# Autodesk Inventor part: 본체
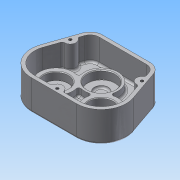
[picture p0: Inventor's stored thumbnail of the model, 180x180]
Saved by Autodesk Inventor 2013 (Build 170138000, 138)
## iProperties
Created: 2014-12
Part Number: 본체
Material: 알루미늄 6061
Document SubType Name: Modeling
Designer: Administrator
Mass: 613.435 g
Surface Area: 665.181 cm^2
Volume: 226.36 cm^3
Density: 2.71 g/cm^3
Author: Administrator
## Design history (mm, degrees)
sketch "스케치1"
  geometry: L1 (0, 32.527)-(-32.527, 0); L2 (0, 32.527)-(32.527, 0); L3 (47, 68.527)-(-47, 68.527); L4 (-66.565, 11.723)-(-47, 68.527); L5 (66.565, 11.723)-(47, 68.527); L6 (-32.527, -36)-(32.527, -36); A1 r 36 centre (-32.527, 0) between (-66.565, 11.723) and (-32.527, -36); A2 r 36 centre (32.527, 0) between (32.527, -36) and (66.565, 11.723); 1 further point
  constraints: 12 end point, 4 point on circle, 4 tangent, 2 centre point, 2 horizontal alignment, 1 equal length, 1 horizontal, 1 vertical alignment
  dimensions: "d0" = 72 diameter of A1; "d1" = 72 diameter of A2; "d3" = 90 deg angle of L1 L2; "d4" = 36 distance from line of L3 L1.start; "d5" = 94 distance of L3.start L3.end; "d25" = 46 distance of L1.start L1.end; "d26" = 46 distance of L1.start L2.end
extrude "돌출1" new body sketch "스케치1" distance "d6" = 44; taper "d7" = 0 deg
fillet "모깎기1" dims "d8" = 18
sketch "스케치2"
  geometry: L1 (-51.181, 56.389)-(-66.565, 11.723) reference; L2 (-32.527, -36)-(32.527, -36) reference; L3 (66.565, 11.723)-(51.181, 56.389) reference; L4 (34.162, 68.527)-(-34.162, 68.527) reference; L5 (-46.453, 54.76)-(-61.837, 10.095); L6 (-32.527, -31)-(32.527, -31); L7 (61.837, 10.095)-(46.453, 54.76); L8 (34.162, 63.527)-(-34.162, 63.527); A1 r 18 centre (-34.162, 50.527) between (-34.162, 68.527) and (-51.181, 56.389) reference; A2 r 36 centre (-32.527, 0) between (-66.565, 11.723) and (-32.527, -36) reference; A3 r 36 centre (32.527, 0) between (32.527, -36) and (66.565, 11.723) reference; A4 r 18 centre (34.162, 50.527) between (51.181, 56.389) and (34.162, 68.527) reference; A5 r 13 centre (-34.162, 50.527) between (-34.162, 63.527) and (-46.453, 54.76); A6 r 31 centre (-32.527, 0) between (-61.837, 10.095) and (-32.527, -31); A7 r 31 centre (32.527, 0) between (32.527, -31) and (61.837, 10.095); A8 r 13 centre (34.162, 50.527) between (46.453, 54.76) and (34.162, 63.527); 1 further point
  constraints: 8 end point, 8 point on circle, 4 centre point, 7 other
  dimensions: "d9" = 5 distance between parallel lines of L4 L8
extrude "돌출2" cut sketch "스케치2" distance "d11" = 34; taper "d12" = 0 deg
sketch "스케치3"
  geometry: L1 (-61.837, 10.095)-(-46.453, 54.76) reference; L2 (32.527, -31)-(-32.527, -31) reference; L3 (46.453, 54.76)-(61.837, 10.095) reference; L4 (-34.162, 68.527)-(34.162, 68.527) reference; A1 r 8 centre (-51.7, 39.527) between (-54.305, 31.963) and (-49.095, 47.091); A2 r 8 centre (51.7, 39.527) between (49.095, 47.091) and (54.305, 31.963); A3 r 8 centre (0, -31) between (8, -31) and (-8, -31); 1 further point
  constraints: 8 point on line, 6 point on circle, 3 centre point, 1 midpoint
  dimensions: "d13" = 16 diameter of A1; "d15" = 16 diameter of A2; "d16" = 29 distance from line of L4 A2.centre; "d17" = 29 distance from line of L4 A1.centre; "d18" = 16 diameter of A3
extrude "돌출3" join sketch "스케치3" distance "d19" = 34; taper "d20" = 0 deg
sketch "스케치4"
  geometry: C1 r 24 at (-32.527, 0); C2 r 24 at (32.527, 0); A1 r 31 centre (32.527, 0) between (32.527, -31) and (61.837, 10.095) reference; A2 r 31 centre (-32.527, 0) between (-61.837, 10.095) and (-32.527, -31) reference; 1 further point
  constraints: 2 centre point, 2 coincident
  dimensions: "d21" = 48 diameter of C1; "d22" = 48 diameter of C2
extrude "돌출4" join sketch "스케치4" distance "d23" = 11; taper "d24" = 0 deg
sketch "스케치5"
  geometry: C1 r 24 at (0, 0) reference; C2 r 24 at (-65.054, 0) reference; 1 further point
hole "구멍1" sketch "스케치5" at (-65.054, 0), (0, 0) diameter "d27" = 15.5; stored, may be unused: countersink angle "d31" = 90 deg, drill point angle "d33" = 0 deg; dims "d28" = 6, "d29" = 35, "d30" = 11, "d32" = 21
sketch "스케치6"
  geometry: C1 r 20 at (-32.527, 0); C2 r 20 at (32.527, 0); A1 r 36 centre (-32.527, 0) between (-66.565, 11.723) and (-32.527, -36) reference; A2 r 36 centre (32.527, 0) between (32.527, -36) and (66.565, 11.723) reference; 1 further point
  constraints: 2 centre point, 2 coincident
  dimensions: "d34" = 40 diameter of C1; "d35" = 40 diameter of C2
extrude "돌출5" join sketch "스케치6" distance "d36" = 7; taper "d37" = -10 deg
sketch "스케치7"
  geometry: C1 r 18.766 at (0, 0) reference; C2 r 18.766 at (65.054, 0) reference; 1 further point
hole "구멍2" sketch "스케치7" at (0, 0), (65.054, 0) diameter "d38" = 30; stored, may be unused: countersink angle "d42" = 90 deg, drill point angle "d44" = 0 deg; dims "d39" = 6, "d40" = 35, "d41" = 11, "d43" = 7
sketch "스케치8"
  geometry: L1 (-32.527, 0)-(0, 32.527); L2 (0, 32.527)-(32.527, 0); C1 r 24 at (0, 32.527); A1 r 31 centre (32.527, 0) between (32.527, -31) and (61.837, 10.095) reference; A2 r 31 centre (-32.527, 0) between (-61.837, 10.095) and (-32.527, -31) reference; 1 further point
  constraints: 4 end point, 1 centre point, 1 coincident, 1 perpendicular, 1 vertical alignment
  dimensions: "d45" = 46 distance of L1.end L2.end; "d46" = 48 diameter of C1
extrude "돌출6" join sketch "스케치8" distance "d47" = 11; taper "d48" = 0 deg
hole "구멍3" diameter "d51" = 20; stored, may be unused: countersink angle "d55" = 90 deg, drill point angle "d57" = 0 deg; dims "d49" = 10, "d50" = 10, "d52" = 6, "d53" = 40, "d54" = 12, "d56" = 15
fillet "모깎기2" dims "d58" = 0.3
fillet "모깎기3" dims "d59" = 0.1
chamfer "모따기1" distance "d60" = 1; stored, may be unused: second distance "d61" = 2, angle "d62" = 45 deg
fillet "모깎기4" dims "d63" = 3
fillet "모깎기5" dims "d64" = 3
fillet "모깎기6" dims "d65" = 3
fillet "모깎기7" dims "d66" = 3
sketch "스케치9"
  geometry: A1 r 8 centre (-51.7, 39.527) between (-52.144, 31.539) and (-47.131, 46.094) reference; A2 r 8 centre (51.7, 39.527) between (47.131, 46.094) and (52.144, 31.539) reference; A3 r 8 centre (0, -31) between (7.697, -28.818) and (-7.697, -28.818) reference; 4 further points
  constraints: 3 coincident
hole "구멍4" sketch "스케치9" at (-51.7, 39.527), (0, -31), (51.7, 39.527) diameter "d67" = 4.134; stored, may be unused: countersink angle "d71" = 90 deg, drill point angle "d73" = 118 deg; dims "d68" = 20, "d69" = 40, "d70" = 12, "d72" = 23
sketch "스케치10"
  geometry: L1 (34.162, 68.527)-(-34.162, 68.527); L2 (51.181, 56.389)-(66.565, 11.723) reference; L3 (32.527, -36)-(-32.527, -36) reference; L4 (-66.565, 11.723)-(-51.181, 56.389) reference; L5 (-34.162, 68.527)-(34.162, 68.527) reference; C1 r 14.9 at (32.527, 0) reference; C2 r 14.9 at (-32.527, 0) reference; C3 r 20 at (-32.527, 0) reference; C4 r 20 at (32.527, 0) reference; C5 r 7.75 at (32.527, 0) reference; C6 r 7.75 at (-32.527, 0) reference; A1 r 18 centre (34.162, 50.527) between (51.181, 56.389) and (34.162, 68.527) reference; A2 r 36 centre (32.527, 0) between (32.527, -36) and (66.565, 11.723) reference; A3 r 36 centre (-32.527, 0) between (-66.565, 11.723) and (-32.527, -36) reference; A4 r 18 centre (-34.162, 50.527) between (-34.162, 68.527) and (-51.181, 56.389) reference; 3 further points
  constraints: 2 end point, 1 coincident, 1 vertical alignment, 1 other
  dimensions: "d74" = 30 distance from line of L1 point (0, 38.527)
feature "엠보싱1" sketch "스케치10" dims "d0" = 72, "d1" = 72, "d3" = 90 deg, "d4" = 36, "d5" = 94, "d7" = 0, "d25" = 46, "d26" = 46, "d75" = 1, "d76" = 0
fillet "모깎기8" dims "d77" = 3
fillet "모깎기9" dims "d78" = 3
node "솔리드1"
node "투영된 루프1"
node "절단 모서리 투영1"
